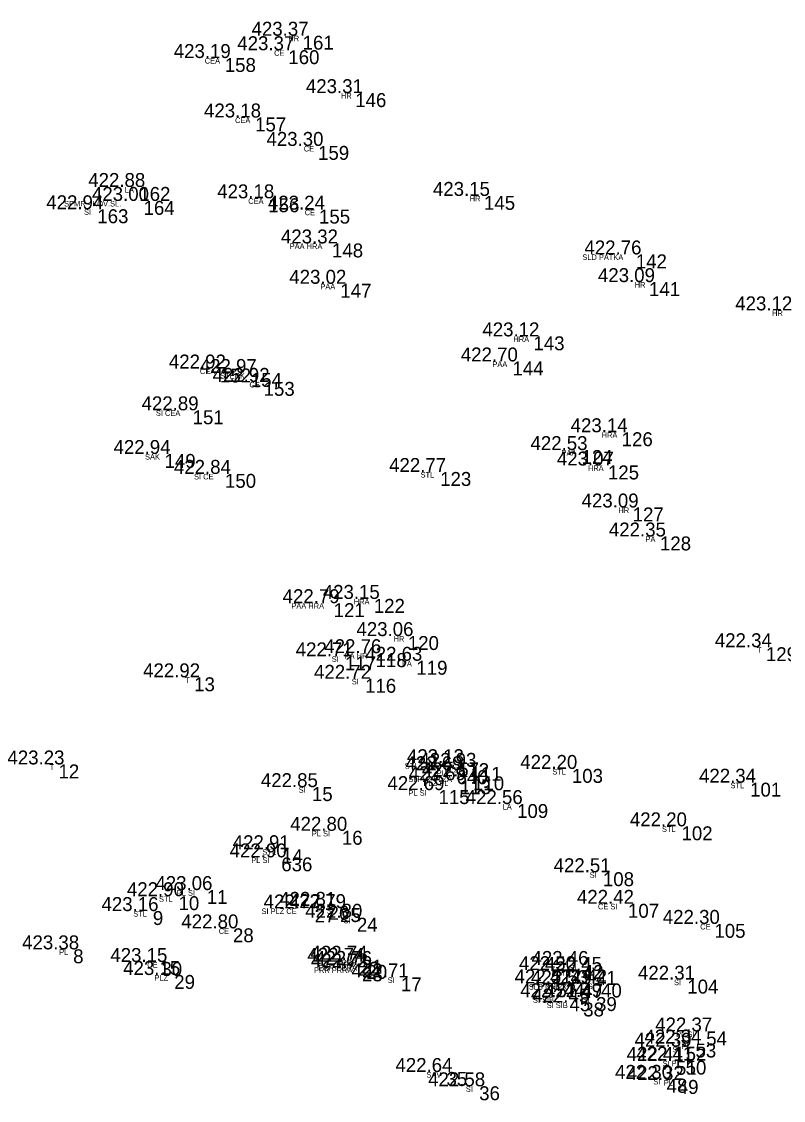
# Model space of a CAD drawing. Extents: x -639373 to -639057, y -1138651 to -1138359.
# Drawn here: x -639142.4 to -639101.4, y -1138649.8 to -1138591.7 of the extents above; entities that cross this region are included whole.
import ezdxf

# ---------------------------------------------------------------- set-up
doc = ezdxf.new("R2010")
doc.units = 0
for name, color, linetype in [('Vrstva 11', 7, 'Continuous'), ('Vrstva 12', 7, 'Continuous'), ('Vrstva 13', 7, 'Continuous'), ('Vrstva 14', 7, 'Continuous'), ('Vrstva 57', 7, 'Continuous')]:
    doc.layers.add(name, color=color, linetype=linetype)

msp = doc.modelspace()

# ---------------------------------------------------------------- linework, layer by layer
at = {"layer": 'Vrstva 11'}
for p, q in [((-639127.58, -1138592.51), (-639127.58, -1138592.51)), ((-639128.35, -1138593.29), (-639128.35, -1138593.29)), ((-639131.77, -1138593.71), (-639131.77, -1138593.71)), ((-639124.75, -1138595.6), (-639124.75, -1138595.6)), ((-639130.14, -1138596.91), (-639130.14, -1138596.91)), ((-639126.75, -1138598.44), (-639126.75, -1138598.44)), ((-639136.37, -1138600.65), (-639136.37, -1138600.65)), ((-639136.14, -1138601.4), (-639136.14, -1138601.4)), ((-639129.43, -1138601.26), (-639129.43, -1138601.26)), ((-639117.82, -1138601.13), (-639117.82, -1138601.13)), ((-639138.63, -1138601.85), (-639138.63, -1138601.85)), ((-639126.7, -1138601.87), (-639126.7, -1138601.87)), ((-639126, -1138603.69), (-639126, -1138603.69)), ((-639109.65, -1138604.28), (-639109.65, -1138604.28)), ((-639125.55, -1138605.86), (-639125.55, -1138605.86)), ((-639108.94, -1138605.77), (-639108.94, -1138605.77)), ((-639101.55, -1138607.29), (-639101.55, -1138607.29)), ((-639115.16, -1138608.69), (-639115.16, -1138608.69)), ((-639116.29, -1138610.04), (-639116.29, -1138610.04)), ((-639132.03, -1138610.42), (-639132.03, -1138610.42)), ((-639130.37, -1138610.66), (-639130.37, -1138610.66)), ((-639129.68, -1138611.14), (-639129.68, -1138611.14)), ((-639133.5, -1138612.67), (-639133.5, -1138612.67)), ((-639110.41, -1138613.85), (-639110.41, -1138613.85)), ((-639112.57, -1138614.81), (-639112.57, -1138614.81)), ((-639135.01, -1138615.02), (-639135.01, -1138615.02)), ((-639131.76, -1138616.09), (-639131.76, -1138616.09)), ((-639120.18, -1138615.99), (-639120.18, -1138615.99)), ((-639111.15, -1138615.64), (-639111.15, -1138615.64)), ((-639109.82, -1138617.9), (-639109.82, -1138617.9)), ((-639108.35, -1138619.46), (-639108.35, -1138619.46)), ((-639125.91, -1138623.05), (-639125.91, -1138623.05)), ((-639123.75, -1138622.82), (-639123.75, -1138622.82)), ((-639121.92, -1138624.82), (-639121.92, -1138624.82)), ((-639102.65, -1138625.42), (-639102.65, -1138625.42)), ((-639125.3, -1138625.91), (-639125.3, -1138625.91)), ((-639123.65, -1138625.74), (-639123.65, -1138625.74)), ((-639121.46, -1138626.15), (-639121.46, -1138626.15)), ((-639133.42, -1138627.04), (-639133.42, -1138627.04)), ((-639124.22, -1138627.12), (-639124.22, -1138627.12)), ((-639140.72, -1138631.73), (-639140.72, -1138631.73)), ((-639119.22, -1138631.66), (-639119.22, -1138631.66)), ((-639119.3, -1138632.04), (-639119.3, -1138632.04)), ((-639118.55, -1138631.86), (-639118.55, -1138631.86)), ((-639118.41, -1138632.37), (-639118.41, -1138632.37)), ((-639113.09, -1138631.97), (-639113.09, -1138631.97)), ((-639127.08, -1138632.95), (-639127.08, -1138632.95)), ((-639119.12, -1138632.58), (-639119.12, -1138632.58)), ((-639103.5, -1138632.71), (-639103.5, -1138632.71)), ((-639120.27, -1138633.11), (-639120.27, -1138633.11)), ((-639116.04, -1138633.86), (-639116.04, -1138633.86)), ((-639125.47, -1138635.3), (-639125.47, -1138635.3)), ((-639107.19, -1138635.06), (-639107.19, -1138635.06)), ((-639128.69, -1138636.29), (-639128.69, -1138636.29)), ((-639128.73, -1138636.73), (-639128.73, -1138636.73)), ((-639111.42, -1138637.53), (-639111.42, -1138637.53)), ((-639132.74, -1138638.49), (-639132.74, -1138638.49)), ((-639134.26, -1138638.82), (-639134.26, -1138638.82)), ((-639126.19, -1138639.34), (-639126.19, -1138639.34)), ((-639110.07, -1138639.23), (-639110.07, -1138639.23)), ((-639135.64, -1138639.62), (-639135.64, -1138639.62)), ((-639126.93, -1138639.48), (-639126.93, -1138639.48)), ((-639125.57, -1138639.46), (-639125.57, -1138639.46)), ((-639131.33, -1138640.55), (-639131.33, -1138640.55)), ((-639124.66, -1138639.98), (-639124.66, -1138639.98)), ((-639105.42, -1138640.31), (-639105.42, -1138640.31)), ((-639139.93, -1138641.68), (-639139.93, -1138641.68)), ((-639124.41, -1138642.24), (-639124.41, -1138642.24)), ((-639135.18, -1138642.36), (-639135.18, -1138642.36)), ((-639124.58, -1138642.35), (-639124.58, -1138642.35)), ((-639124.39, -1138642.65), (-639124.39, -1138642.65)), ((-639124.15, -1138642.52), (-639124.15, -1138642.52)), ((-639113.16, -1138642.8), (-639113.16, -1138642.8)), ((-639112.5, -1138642.52), (-639112.5, -1138642.52)), ((-639111.79, -1138642.84), (-639111.79, -1138642.84)), ((-639134.49, -1138643.06), (-639134.49, -1138643.06)), ((-639122.29, -1138643.19), (-639122.29, -1138643.19)), ((-639106.88, -1138643.31), (-639106.88, -1138643.31)), ((-639113.52, -1138643.51), (-639113.52, -1138643.51)), ((-639112.54, -1138643.55), (-639112.54, -1138643.55)), ((-639111.52, -1138643.52), (-639111.52, -1138643.52)), ((-639113.22, -1138644.26), (-639113.22, -1138644.26)), ((-639112.48, -1138644.54), (-639112.48, -1138644.54)), ((-639111.79, -1138644.25), (-639111.79, -1138644.25)), ((-639105.86, -1138646.1), (-639105.86, -1138646.1)), ((-639106.97, -1138646.92), (-639106.97, -1138646.92)), ((-639106.44, -1138646.75), (-639106.44, -1138646.75)), ((-639107.49, -1138647.68), (-639107.49, -1138647.68)), ((-639106.97, -1138647.67), (-639106.97, -1138647.67)), ((-639119.84, -1138648.28), (-639119.84, -1138648.28)), ((-639107.99, -1138648.65), (-639107.99, -1138648.65)), ((-639118.08, -1138649.05), (-639118.08, -1138649.05)), ((-639107.39, -1138648.71), (-639107.39, -1138648.71))]:
    msp.add_line(p, q, dxfattribs=at)

# ---------------------------------------------------------------- texts
at = {"layer": 'Vrstva 12'}
for s, p in [('422.88 ', (-639138.839, -1138600.65)), ('423.00 ', (-639138.639, -1138601.4)), ('423.32 ', (-639128.469, -1138603.69)), ('422.76 ', (-639112.136, -1138604.28)), ('423.02 ', (-639128.019, -1138605.86)), ('423.12 ', (-639117.629, -1138608.69)), ('422.70 ', (-639118.789, -1138610.04)), ('423.14 ', (-639112.879, -1138613.85)), ('422.53 ', (-639115.039, -1138614.81)), ('423.07 ', (-639113.619, -1138615.64)), ('423.09 ', (-639112.289, -1138617.9)), ('422.35 ', (-639110.82, -1138619.46)), ('422.79 ', (-639128.379, -1138623.05)), ('423.15 ', (-639126.22, -1138622.82)), ('423.06 ', (-639124.406, -1138624.82)), ('422.34 ', (-639105.119, -1138625.42)), ('422.76 ', (-639126.136, -1138625.74)), ('422.63 ', (-639123.929, -1138626.15)), ('423.13 ', (-639121.689, -1138631.66)), ('422.20 ', (-639115.589, -1138631.97)), ('422.34 ', (-639105.969, -1138632.71)), ('422.56 ', (-639118.526, -1138633.86)), ('422.20 ', (-639109.689, -1138635.06)), ('422.90 ', (-639131.229, -1138636.73)), ('422.51 ', (-639113.795, -1138637.53)), ('423.06 ', (-639135.226, -1138638.49)), ('422.77 ', (-639129.399, -1138639.48)), ('422.81 ', (-639128.565, -1138639.34)), ('422.79 ', (-639128.039, -1138639.46)), ('422.42 ', (-639112.539, -1138639.23)), ('422.80 ', (-639127.159, -1138639.98)), ('422.80 ', (-639133.829, -1138640.55)), ('422.30 ', (-639107.919, -1138640.31)), ('423.38 ', (-639142.399, -1138641.68)), ('423.15 ', (-639137.65, -1138642.36)), ('422.74 ', (-639127.049, -1138642.35)), ('422.74 ', (-639126.879, -1138642.24)), ('423.15 ', (-639136.96, -1138643.06)), ('422.72 ', (-639126.859, -1138642.65)), ('422.76 ', (-639126.636, -1138642.52)), ('422.50 ', (-639115.659, -1138642.8)), ('422.46 ', (-639114.986, -1138642.52)), ('422.45 ', (-639114.26, -1138642.84)), ('422.71 ', (-639124.665, -1138643.19)), ('422.51 ', (-639115.895, -1138643.51)), ('422.53 ', (-639115.009, -1138643.55)), ('422.42 ', (-639113.989, -1138643.52)), ('422.31 ', (-639109.255, -1138643.31)), ('422.51 ', (-639115.595, -1138644.26)), ('422.45 ', (-639114.95, -1138644.54)), ('422.49 ', (-639114.259, -1138644.25)), ('422.37 ', (-639108.329, -1138646.1)), ('422.39 ', (-639109.439, -1138646.92)), ('422.34 ', (-639108.909, -1138646.75)), ('422.41 ', (-639109.865, -1138647.68)), ('422.41 ', (-639109.345, -1138647.67)), ('422.64 ', (-639122.309, -1138648.28)), ('422.30 ', (-639110.489, -1138648.65)), ('422.32 ', (-639109.859, -1138648.71)), ('422.58 ', (-639120.549, -1138649.05))]:
    msp.add_text(s, height=0.75, dxfattribs=at).set_placement(p)
at = {"layer": 'Vrstva 13'}
for s, p in [(' 161', (-639127.58, -1138593.26)), (' 160', (-639128.35, -1138594.04)), (' 158', (-639131.77, -1138594.46)), (' 146', (-639124.75, -1138596.35)), (' 157', (-639130.14, -1138597.66)), (' 159', (-639126.75, -1138599.19)), (' 162', (-639136.37, -1138601.4)), (' 164', (-639136.14, -1138602.15)), (' 156', (-639129.43, -1138602.01)), (' 145', (-639117.82, -1138601.88)), (' 163', (-639138.63, -1138602.6)), (' 155', (-639126.7, -1138602.62)), (' 148', (-639126, -1138604.44)), (' 142', (-639109.65, -1138605.03)), (' 147', (-639125.55, -1138606.61)), (' 141', (-639108.94, -1138606.52)), (' 143', (-639115.16, -1138609.44)), (' 144', (-639116.29, -1138610.79)), (' 152', (-639132.03, -1138611.17)), (' 154', (-639130.37, -1138611.41)), (' 153', (-639129.68, -1138611.89)), (' 151', (-639133.5, -1138613.42)), (' 126', (-639110.41, -1138614.6)), (' 149', (-639135.01, -1138615.77)), (' 124', (-639112.57, -1138615.56)), (' 150', (-639131.76, -1138616.84)), (' 123', (-639120.18, -1138616.74)), (' 125', (-639111.15, -1138616.39)), (' 127', (-639109.82, -1138618.65)), (' 128', (-639108.35, -1138620.21)), (' 121', (-639125.91, -1138623.8)), (' 122', (-639123.75, -1138623.57)), (' 120', (-639121.92, -1138625.57)), (' 129', (-639102.65, -1138626.17)), (' 117', (-639125.3, -1138626.66)), (' 118', (-639123.65, -1138626.49)), (' 119', (-639121.46, -1138626.9)), (' 13', (-639133.42, -1138627.79)), (' 116', (-639124.22, -1138627.87)), (' 12', (-639140.72, -1138632.48)), (' 112', (-639119.22, -1138632.41)), (' 640', (-639119.3, -1138632.79)), (' 111', (-639118.55, -1138632.61)), (' 110', (-639118.41, -1138633.12)), (' 103', (-639113.09, -1138632.72)), (' 15', (-639127.08, -1138633.7)), (' 113', (-639119.12, -1138633.33)), (' 101', (-639103.5, -1138633.46)), (' 115', (-639120.27, -1138633.86)), (' 109', (-639116.04, -1138634.61)), (' 16', (-639125.47, -1138636.05)), (' 102', (-639107.19, -1138635.81)), (' 14', (-639128.69, -1138637.04)), (' 636', (-639128.73, -1138637.48)), (' 108', (-639111.42, -1138638.28)), (' 10', (-639134.26, -1138639.57)), (' 11', (-639132.74, -1138639.24)), (' 26', (-639126.19, -1138640.09)), (' 107', (-639110.07, -1138639.98)), (' 9', (-639135.64, -1138640.37)), (' 27', (-639126.93, -1138640.23)), (' 25', (-639125.57, -1138640.21)), (' 24', (-639124.66, -1138640.73)), (' 28', (-639131.33, -1138641.3)), (' 105', (-639105.42, -1138641.06)), (' 8', (-639139.93, -1138642.43)), (' 21', (-639124.41, -1138642.99)), (' 30', (-639135.18, -1138643.11)), (' 22', (-639124.58, -1138643.1)), (' 23', (-639124.39, -1138643.4)), (' 20', (-639124.15, -1138643.27)), (' 43', (-639113.16, -1138643.55)), (' 42', (-639112.5, -1138643.27)), (' 41', (-639111.79, -1138643.59)), (' 29', (-639134.49, -1138643.81)), (' 17', (-639122.29, -1138643.94)), (' 104', (-639106.88, -1138644.06)), (' 44', (-639113.52, -1138644.26)), (' 47', (-639112.54, -1138644.3)), (' 40', (-639111.52, -1138644.27)), (' 45', (-639113.22, -1138645.01)), (' 38', (-639112.48, -1138645.29)), (' 39', (-639111.79, -1138645)), (' 54', (-639105.86, -1138646.85)), (' 52', (-639106.97, -1138647.67)), (' 53', (-639106.44, -1138647.5)), (' 51', (-639107.49, -1138648.43)), (' 50', (-639106.97, -1138648.42)), (' 35', (-639119.84, -1138649.03)), (' 48', (-639107.99, -1138649.4)), (' 36', (-639118.08, -1138649.8)), (' 49', (-639107.39, -1138649.46))]:
    msp.add_text(s, height=0.75, dxfattribs=at).set_placement(p)
at = {"layer": 'Vrstva 14'}
for s, p in [('423.37 ', (-639130.049, -1138592.51)), ('423.19 ', (-639134.239, -1138593.71)), ('423.37 ', (-639130.819, -1138593.29)), ('423.31 ', (-639127.125, -1138595.6)), ('423.18 ', (-639132.609, -1138596.91)), ('423.30 ', (-639129.249, -1138598.44)), ('423.15 ', (-639120.29, -1138601.13)), ('423.18 ', (-639131.899, -1138601.26)), ('422.94 ', (-639141.099, -1138601.85)), ('423.24 ', (-639129.169, -1138601.87)), ('423.09 ', (-639111.409, -1138605.77)), ('423.12 ', (-639104.019, -1138607.29)), ('422.92 ', (-639134.499, -1138610.42)), ('422.97 ', (-639132.839, -1138610.66)), ('422.92 ', (-639132.149, -1138611.14)), ('422.89 ', (-639135.969, -1138612.67)), ('422.94 ', (-639137.479, -1138615.02)), ('422.84 ', (-639134.229, -1138616.09)), ('422.77 ', (-639122.649, -1138615.99)), ('422.71 ', (-639127.675, -1138625.91)), ('422.92 ', (-639135.889, -1138627.04)), ('422.72 ', (-639126.689, -1138627.12)), ('423.23 ', (-639143.189, -1138631.73)), ('422.93 ', (-639121.019, -1138631.86)), ('422.69 ', (-639121.769, -1138632.04)), ('422.69 ', (-639121.589, -1138632.58)), ('422.57 ', (-639120.879, -1138632.37)), ('422.85 ', (-639129.55, -1138632.95)), ('422.69 ', (-639122.739, -1138633.11)), ('422.80 ', (-639127.969, -1138635.3)), ('422.91 ', (-639131.065, -1138636.29)), ('422.90 ', (-639136.759, -1138638.82)), ('423.16 ', (-639138.126, -1138639.62))]:
    msp.add_text(s, height=0.75, dxfattribs=at).set_placement(p)
at = {"layer": 'Vrstva 57'}
for s, p in [('HR', (-639128.069, -1138592.81)), ('CE', (-639128.838, -1138593.59)), ('CEA', (-639132.57, -1138594.01)), ('HR', (-639125.239, -1138595.9)), ('CEA', (-639130.94, -1138597.21)), ('CE', (-639127.238, -1138598.74)), ('LA', (-639136.87, -1138600.95)), ('SPMR - KOV.SL.', (-639140.139, -1138601.7)), ('CEA', (-639130.23, -1138601.56)), ('HR', (-639118.309, -1138601.43)), ('SI', (-639139.068, -1138602.15)), ('CE', (-639127.188, -1138602.17)), ('PAA HRA', (-639128, -1138603.99)), ('SLD PATKA', (-639112.25, -1138604.58)), ('PAA', (-639126.35, -1138606.16)), ('HR', (-639109.429, -1138606.07)), ('HR', (-639102.039, -1138607.59)), ('HRA', (-639115.96, -1138608.99)), ('PAA', (-639117.09, -1138610.34)), ('CEA', (-639132.83, -1138610.72)), ('STERK', (-639131.745, -1138610.96)), ('CE', (-639130.167, -1138611.44)), ('SI CEA', (-639135.2, -1138612.97)), ('HRA', (-639111.21, -1138614.15)), ('PAA', (-639113.37, -1138615.11)), ('SAK', (-639135.785, -1138615.32)), ('SI CE', (-639133.147, -1138616.39)), ('STL', (-639120.955, -1138616.29)), ('HRA', (-639111.95, -1138615.94)), ('HR', (-639110.309, -1138618.2)), ('PA', (-639108.85, -1138619.76)), ('PAA HRA', (-639127.91, -1138623.35)), ('HRA', (-639124.55, -1138623.12)), ('HR', (-639122.409, -1138625.12)), ('T', (-639102.85, -1138625.72)), ('SI', (-639125.738, -1138626.21)), ('PA HR', (-639125.039, -1138626.04)), ('PA', (-639121.96, -1138626.45)), ('T', (-639133.62, -1138627.34)), ('SI', (-639124.658, -1138627.42)), ('T', (-639140.92, -1138632.03)), ('STL - KER', (-639121.809, -1138631.96)), ('SI PLZ PLZA', (-639121.61, -1138632.67)), ('PLZ', (-639120.089, -1138632.34)), ('PLZA', (-639119.65, -1138632.16)), ('STL', (-639113.865, -1138632.27)), ('SI', (-639127.518, -1138633.25)), ('PLZ PL', (-639120.795, -1138632.88)), ('STL', (-639104.275, -1138633.01)), ('PL SI', (-639121.608, -1138633.41)), ('LA', (-639116.54, -1138634.16)), ('PL SI', (-639126.808, -1138635.6)), ('STL', (-639107.965, -1138635.36)), ('STL', (-639129.465, -1138636.59)), ('PL SI', (-639130.068, -1138637.03)), ('SI', (-639111.858, -1138637.83)), ('STL', (-639135.035, -1138639.12)), ('PL SI', (-639134.078, -1138638.79)), ('SI', (-639126.628, -1138639.64)), ('CE SI', (-639111.408, -1138639.53)), ('STL', (-639136.415, -1138639.92)), ('SI PLZ CE', (-639129.517, -1138639.78)), ('SI', (-639126.008, -1138639.76)), ('SI', (-639125.098, -1138640.28)), ('CE', (-639131.818, -1138640.85)), ('CE', (-639105.907, -1138640.61)), ('PL', (-639140.405, -1138641.98)), ('PRR', (-639125.199, -1138642.54)), ('CE', (-639135.667, -1138642.66)), ('PRR PRRA', (-639126.69, -1138642.95)), ('PRR PRRA', (-639126.45, -1138642.82)), ('PRR', (-639125.369, -1138642.65)), ('SI', (-639113.598, -1138643.1)), ('SI', (-639112.938, -1138642.82)), ('SI', (-639112.228, -1138643.14)), ('PLZ', (-639135.279, -1138643.36)), ('SI', (-639122.728, -1138643.49)), ('SI', (-639107.318, -1138643.61)), ('SLB NN 2X', (-639115.128, -1138643.85)), ('SI', (-639113.958, -1138643.81)), ('SI', (-639111.958, -1138643.82)), ('SI SIB', (-639114.909, -1138644.56)), ('SI SIB', (-639114.169, -1138644.84)), ('SI', (-639112.228, -1138644.55)), ('PL SI', (-639107.198, -1138646.4)), ('SI', (-639107.408, -1138647.22)), ('PL', (-639106.915, -1138647.05)), ('SI', (-639107.928, -1138647.98)), ('PL', (-639107.445, -1138647.97)), ('SAV', (-639120.64, -1138648.58)), ('SI', (-639108.428, -1138648.95)), ('SI', (-639118.518, -1138649.35)), ('PL', (-639107.865, -1138649.01))]:
    msp.add_text(s, height=0.3, dxfattribs=at).set_placement(p)

doc.saveas('drawing.dxf')
